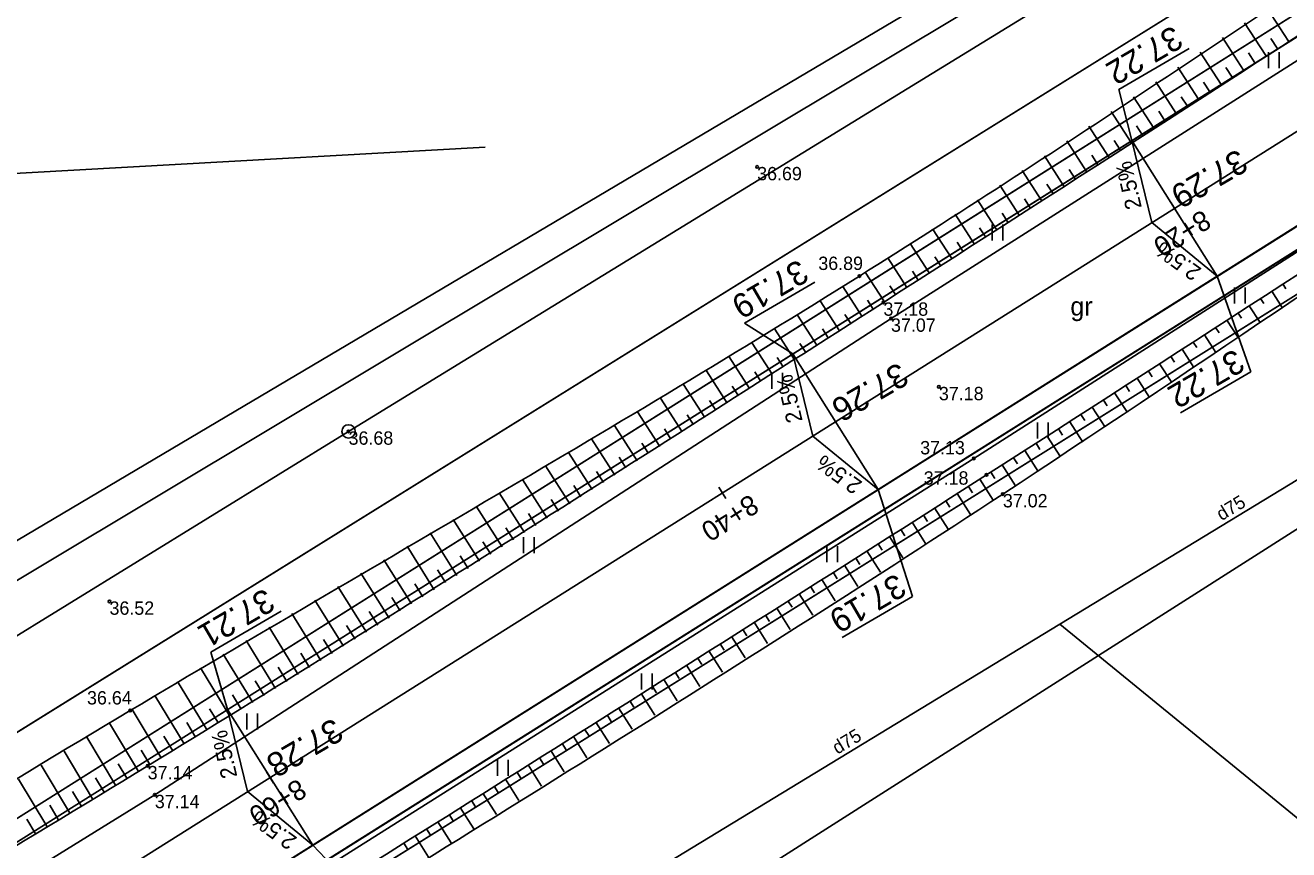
# Model space of a CAD drawing. Extents: x 469981 to 472086, y 246785 to 247785.
# Drawn here: x 471212.38 to 471259.67, y 247263.46 to 247294.34 of the extents above; entities that cross this region are included whole.
import ezdxf

# ---------------------------------------------------------------- set-up
doc = ezdxf.new("R2010")
doc.units = 0
for name, color, linetype in [('0_922', 7, 'Continuous'), ('0_Asfalta_mala', 7, 'Continuous'), ('0_Asfalta_Nomale', 7, 'Continuous'), ('0_Ruut_Braukt', 7, 'Continuous'), ('0_Ruut_nomale', 7, 'Continuous'), ('0_vertikals', 7, 'Continuous'), ('0_vertkals_cipari', 7, 'Continuous'), ('21', 7, 'Continuous'), ('6_piketaza', 7, 'Continuous'), ('CELI_CMAL_####_####_#', 7, 'Continuous'), ('CELI_CSEG_####_TKST_#', 7, 'Continuous'), ('DREN_VADP_####_####_#', 7, 'Continuous'), ('DREN_VADP_KLKT_####_#', 7, 'Continuous'), ('DREN_VADP_KLKT_TKST_#', 7, 'Continuous'), ('ELEK_ELEM_####_####_#', 7, 'Continuous'), ('ELEK_VADV_VSPR_####_#', 7, 'Continuous'), ('RAMI_UZMR_####_####_#', 7, 'Continuous'), ('RELJ_AATZ_####_TKST_#', 7, 'Continuous'), ('RELJ_ELEM_####_####_#', 7, 'Continuous'), ('RELJ_NOGA_####_####_#', 7, 'Continuous'), ('RELJ_NOGL_####_####_#', 7, 'Continuous'), ('ROBZ_IERR_####_####_#', 7, 'Continuous'), ('ROBZ_PROJ_####_####_#', 7, 'Continuous'), ('TERT_ELEM_####_####_#', 7, 'Continuous')]:
    doc.layers.add(name, color=color, linetype=linetype)

msp = doc.modelspace()

# ---------------------------------------------------------------- linework, layer by layer
at = {"layer": '0_922'}
msp.add_line((471337.911, 247339.41), (471145.574, 247218.36), dxfattribs=at)
at = {"layer": '0_Asfalta_mala'}
for p, q in [((471336.304, 247341.944), (471143.977, 247220.899)), ((471339.517, 247336.876), (471147.172, 247215.821))]:
    msp.add_line(p, q, dxfattribs=at)
at = {"layer": '0_Asfalta_Nomale'}
for p, q in [((471335.903, 247342.577), (471143.577, 247221.534)), ((471339.918, 247336.243), (471147.572, 247215.187))]:
    msp.add_line(p, q, dxfattribs=at)
at = {"layer": '0_Ruut_Braukt'}
for p, q in [((471336.304, 247341.944), (471143.977, 247220.899)), ((471147.172, 247215.821), (471339.517, 247336.876))]:
    msp.add_line(p, q, dxfattribs=at)
at = {"layer": '0_Ruut_nomale'}
for points in [[(471512.083, 247454.162), (471511.838, 247454.895), (471453.013, 247417.341), (471348.58, 247350.671), (471335.903, 247342.577), (471306.296, 247323.944), (471248.242, 247287.407), (471208.75, 247262.551), (471208.786, 247261.688), (471290.39, 247313.047), (471335.822, 247341.64), (471349.818, 247350.571), (471398.518, 247381.661), (471437.5, 247406.548), (471498.795, 247445.679), (471511.425, 247453.742)], [(471514.294, 247447.566), (471399.037, 247373.985), (471385.85, 247365.566), (471340.791, 247336.792), (471211.253, 247255.265), (471209.116, 247253.92), (471209.079, 247254.783), (471296.254, 247309.648), (471339.517, 247336.876), (471350.75, 247344.048), (471392.723, 247370.844), (471426.479, 247392.394), (471514.049, 247448.299)]]:
    msp.add_lwpolyline(points, close=True, dxfattribs=at)
at = {"layer": '0_vertikals'}
for p, q in [((471253.314, 247291.937), (471255.945, 247293.472)), ((471253.799, 247290.018), (471253.314, 247291.937)), ((471258.255, 247281.359), (471256.995, 247284.94)), ((471239.303, 247283.18), (471241.935, 247284.715)), ((471241.104, 247282.028), (471239.303, 247283.18)), ((471255.624, 247279.825), (471258.255, 247281.359)), ((471245.589, 247272.951), (471244.3, 247276.95)), ((471242.957, 247271.417), (471245.589, 247272.951)), ((471219.325, 247270.863), (471221.957, 247272.398)), ((471219.945, 247268.712), (471219.325, 247270.863)), ((471225.923, 247260.712), (471223.141, 247263.634))]:
    msp.add_line(p, q, dxfattribs=at)
for points in [[(471253.799, 247290.018), (471254.55, 247286.946), (471256.995, 247284.94)], [(471241.104, 247282.028), (471241.855, 247278.956), (471244.3, 247276.95)], [(471219.945, 247268.712), (471220.697, 247265.64), (471223.141, 247263.634)]]:
    msp.add_lwpolyline(points, close=True, dxfattribs=at)
at = {"layer": '21'}
msp.add_line((471337.911, 247339.41), (471145.574, 247218.36), dxfattribs=at)
at = {"layer": '6_piketaza'}
for points in [[(471255.53, 247287.267), (471255.264, 247287.69)], [(471238.603, 247276.614), (471238.337, 247277.037)], [(471221.677, 247265.961), (471221.41, 247266.384)]]:
    msp.add_lwpolyline(points, dxfattribs=at)
at = {"layer": 'CELI_CMAL_####_####_#'}
for points in [[(471014.161, 247188.048), (471038.308, 247191.645), (471077.61, 247195.71), (471090.836, 247197.337), (471096.461, 247198.582), (471117.856, 247206.682), (471130.197, 247213.261), (471151.631, 247225.738), (471175.407, 247239.608), (471196.168, 247252.49), (471217.229, 247265.52), (471244.784, 247283.359), (471266.102, 247296.914), (471293.433, 247314.365), (471318.262, 247330.084), (471336.637, 247341.969), (471339.45, 247343.841), (471340.412, 247346.293), (471340.291, 247349.818), (471339.894, 247353.24), (471336.901, 247360.015), (471333.813, 247367.721)], [(471347.348, 247327.622), (471345.475, 247334.467), (471344.349, 247336.664), (471343.67, 247337.19), (471342.054, 247337.492), (471341.155, 247337.494), (471339.762, 247336.569), (471318.941, 247323.623), (471297.221, 247309.64), (471268.834, 247291.51), (471247.888, 247278.119), (471219.179, 247259.989), (471200.048, 247247.93), (471177.515, 247234.149), (471154.773, 247220.961), (471131.272, 247207.521), (471119.66, 247201.466), (471103.03, 247195.231), (471092.329, 247192.658), (471077.436, 247189.782), (471058.729, 247187.944), (471037.006, 247184.759), (471015.923, 247182.598), (470992.26, 247181.035)]]:
    msp.add_lwpolyline(points, dxfattribs=at)
at = {"layer": 'DREN_VADP_####_####_#'}
for points in [[(471137.599, 247228.901), (471310.269, 247332.452)], [(471229.592, 247289.778), (471189.418, 247287.521)], [(471271.382, 247255.353), (471251.107, 247271.912)]]:
    msp.add_lwpolyline(points, dxfattribs=at)
at = {"layer": 'DREN_VADP_KLKT_####_#'}
msp.add_lwpolyline([(471222.566, 247254.545), (471236.742, 247263.171), (471251.107, 247271.912), (471265.735, 247280.811), (471282.069, 247290.749), (471296.434, 247299.489), (471310.919, 247308.304), (471326.918, 247318.037)], dxfattribs=at)
at = {"layer": 'ELEK_ELEM_####_####_#'}
msp.add_circle((471224.48, 247279.13), 0.25, dxfattribs=at)
at = {"layer": 'ELEK_VADV_VSPR_####_#'}
for p, q in [((471224.48, 247279.13), (471279.662, 247313.004)), ((471169.047, 247244.988), (471224.48, 247279.13))]:
    msp.add_line(p, q, dxfattribs=at)
at = {"layer": 'RAMI_UZMR_####_####_#'}
for points in [[(471010.572, 247199.465), (471044.448, 247201.846), (471094.566, 247205.368), (471219.251, 247279.294), (471287.982, 247320.045), (471329.582, 247346.385), (471332.466, 247352.407), (471329.951, 247358.592), (471331.784, 247361.204), (471339.558, 247364.746), (471343.514, 247360.959), (471346.629, 247357.978), (471355.9, 247363.1), (471457.4, 247429.3)], [(471380.292, 247353.371), (471352.036, 247335.759), (471352.913, 247327.325), (471347.47, 247325.392), (471345.187, 247325.919), (471342.905, 247329.082), (471319.551, 247313.443), (471222.661, 247251.69), (471157.352, 247211.35), (471144.207, 247202.916), (471131.364, 247196.59), (471113.303, 247188.858), (471105.677, 247188.256), (471083.576, 247183.01), (471075.205, 247182.665), (471043.397, 247175.418), (471016.707, 247172.079), (470997.217, 247171.376)]]:
    msp.add_lwpolyline(points, dxfattribs=at)
at = {"layer": 'RELJ_ELEM_####_####_#'}
for centre in [(471239.774, 247289.031), (471243.601, 247284.946), (471244.501, 247283.959), (471244.784, 247283.359), (471246.577, 247280.796), (471224.48, 247279.13), (471247.888, 247278.119), (471248.359, 247277.5), (471248.971, 247276.784), (471215.532, 247272.762), (471216.311, 247268.677), (471216.962, 247266.603), (471217.229, 247265.52)]:
    msp.add_circle(centre, 0.05, dxfattribs=at)
at = {"layer": 'RELJ_NOGA_####_####_#'}
for p, q in [((471259.656, 247293.747), (471258.852, 247294.988)), ((471258.816, 247293.203), (471258.02, 247294.434)), ((471257.977, 247292.66), (471257.188, 247293.88)), ((471259.236, 247293.475), (471258.996, 247293.846)), ((471257.137, 247292.117), (471256.355, 247293.325)), ((471258.396, 247292.932), (471258.159, 247293.299)), ((471256.297, 247291.574), (471255.523, 247292.771)), ((471257.557, 247292.389), (471257.321, 247292.753)), ((471255.457, 247291.031), (471254.691, 247292.217)), ((471256.717, 247291.845), (471256.484, 247292.206)), ((471254.618, 247290.488), (471253.858, 247291.663)), ((471255.877, 247291.302), (471255.646, 247291.66)), ((471253.778, 247289.945), (471253.025, 247291.109)), ((471255.038, 247290.76), (471254.809, 247291.114)), ((471252.938, 247289.402), (471252.193, 247290.556)), ((471254.198, 247290.217), (471253.971, 247290.567)), ((471252.098, 247288.86), (471251.359, 247290.004)), ((471253.358, 247289.674), (471253.133, 247290.021)), ((471251.258, 247288.317), (471250.525, 247289.453)), ((471252.518, 247289.131), (471252.295, 247289.476)), ((471250.418, 247287.775), (471249.69, 247288.902)), ((471251.678, 247288.588), (471251.457, 247288.93)), ((471249.578, 247287.232), (471248.854, 247288.353)), ((471250.838, 247288.046), (471250.619, 247288.385)), ((471248.737, 247286.69), (471248.018, 247287.805)), ((471249.998, 247287.504), (471249.78, 247287.841)), ((471247.897, 247286.148), (471247.181, 247287.258)), ((471249.158, 247286.961), (471248.941, 247287.297)), ((471248.317, 247286.419), (471248.102, 247286.753)), ((471247.057, 247285.606), (471246.343, 247286.713)), ((471246.216, 247285.064), (471245.504, 247286.169)), ((471247.477, 247285.877), (471247.263, 247286.21)), ((471245.376, 247284.523), (471244.664, 247285.627)), ((471246.636, 247285.335), (471246.423, 247285.667)), ((471244.535, 247283.981), (471243.822, 247285.087)), ((471245.796, 247284.794), (471245.582, 247285.125)), ((471243.695, 247283.439), (471242.979, 247284.55)), ((471244.955, 247284.252), (471244.742, 247284.583)), ((471259.452, 247284.649), (471259.568, 247284.471)), ((471242.854, 247282.898), (471242.133, 247284.016)), ((471244.115, 247283.71), (471243.901, 247284.043)), ((471258.613, 247284.105), (471258.733, 247283.921)), ((471259.033, 247284.377), (471259.424, 247283.773)), ((471242.013, 247282.356), (471241.285, 247283.486)), ((471243.274, 247283.169), (471243.059, 247283.503)), ((471257.774, 247283.561), (471257.897, 247283.37)), ((471258.194, 247283.833), (471258.599, 247283.208)), ((471256.935, 247283.017), (471257.062, 247282.82)), ((471257.354, 247283.289), (471257.772, 247282.644)), ((471241.173, 247281.814), (471240.435, 247282.96)), ((471242.434, 247282.627), (471242.216, 247282.964)), ((471256.515, 247282.745), (471256.946, 247282.08)), ((471240.332, 247281.273), (471239.582, 247282.436)), ((471241.593, 247282.085), (471241.373, 247282.426)), ((471255.676, 247282.202), (471256.119, 247281.517)), ((471256.095, 247282.473), (471256.226, 247282.271)), ((471239.491, 247280.731), (471238.728, 247281.916)), ((471240.752, 247281.544), (471240.529, 247281.89)), ((471254.836, 247281.659), (471255.29, 247280.956)), ((471255.256, 247281.93), (471255.39, 247281.722)), ((471238.65, 247280.19), (471237.873, 247281.399)), ((471239.912, 247281.002), (471239.685, 247281.354)), ((471253.996, 247281.117), (471254.461, 247280.396)), ((471254.416, 247281.388), (471254.554, 247281.174)), ((471237.81, 247279.649), (471237.015, 247280.884)), ((471239.071, 247280.461), (471238.84, 247280.82)), ((471253.576, 247280.845), (471253.716, 247280.627)), ((471236.968, 247279.108), (471236.157, 247280.371)), ((471238.23, 247279.92), (471237.994, 247280.286)), ((471252.735, 247280.304), (471252.879, 247280.081)), ((471253.155, 247280.575), (471253.63, 247279.838)), ((471236.127, 247278.568), (471235.297, 247279.861)), ((471237.389, 247279.379), (471237.148, 247279.753)), ((471251.894, 247279.763), (471252.04, 247279.536)), ((471252.314, 247280.033), (471252.797, 247279.282)), ((471235.285, 247278.029), (471234.437, 247279.352)), ((471236.547, 247278.838), (471236.302, 247279.222)), ((471251.053, 247279.222), (471251.2, 247278.992)), ((471251.473, 247279.492), (471251.964, 247278.73)), ((471234.443, 247277.489), (471233.575, 247278.846)), ((471250.632, 247278.952), (471251.127, 247278.179)), ((471233.6, 247276.951), (471232.713, 247278.34)), ((471235.706, 247278.298), (471235.454, 247278.691)), ((471249.789, 247278.413), (471250.289, 247277.633)), ((471250.211, 247278.683), (471250.36, 247278.45)), ((471232.757, 247276.413), (471231.85, 247277.836)), ((471234.864, 247277.759), (471234.606, 247278.161)), ((471248.947, 247277.875), (471249.448, 247277.089)), ((471249.368, 247278.144), (471249.518, 247277.909)), ((471231.914, 247275.875), (471230.986, 247277.333)), ((471234.022, 247277.22), (471233.758, 247277.632)), ((471248.103, 247277.337), (471248.605, 247276.55)), ((471248.525, 247277.606), (471248.676, 247277.37)), ((471231.07, 247275.339), (471230.122, 247276.831)), ((471233.179, 247276.681), (471232.909, 247277.103)), ((471247.682, 247277.069), (471247.832, 247276.833)), ((471232.336, 247276.144), (471232.06, 247276.576)), ((471246.838, 247276.532), (471246.989, 247276.295)), ((471247.26, 247276.8), (471247.762, 247276.012)), ((471230.226, 247274.803), (471229.258, 247276.329)), ((471231.492, 247275.607), (471231.211, 247276.049)), ((471245.994, 247275.996), (471246.145, 247275.758)), ((471246.416, 247276.264), (471246.918, 247275.474)), ((471229.381, 247274.268), (471228.395, 247275.828)), ((471230.648, 247275.071), (471230.361, 247275.524)), ((471245.15, 247275.459), (471245.301, 247275.222)), ((471245.572, 247275.727), (471246.075, 247274.936)), ((471228.535, 247273.734), (471227.531, 247275.327)), ((471229.803, 247274.535), (471229.51, 247274.998)), ((471244.728, 247275.191), (471245.231, 247274.399)), ((471227.689, 247273.201), (471226.668, 247274.826)), ((471228.958, 247274.001), (471228.659, 247274.474)), ((471243.884, 247274.655), (471244.387, 247273.861)), ((471244.306, 247274.923), (471244.457, 247274.685)), ((471226.842, 247272.67), (471225.805, 247274.323)), ((471243.039, 247274.12), (471243.543, 247273.325)), ((471243.461, 247274.388), (471243.613, 247274.149)), ((471225.994, 247272.139), (471224.943, 247273.822)), ((471228.112, 247273.468), (471227.808, 247273.95)), ((471242.194, 247273.585), (471242.699, 247272.788)), ((471242.617, 247273.852), (471242.768, 247273.613)), ((471225.146, 247271.609), (471224.081, 247273.319)), ((471227.266, 247272.935), (471226.957, 247273.427)), ((471241.35, 247273.049), (471241.855, 247272.252)), ((471241.772, 247273.317), (471241.923, 247273.078)), ((471224.297, 247271.081), (471223.22, 247272.815)), ((471226.418, 247272.404), (471226.105, 247272.905)), ((471240.927, 247272.782), (471241.079, 247272.543)), ((471223.447, 247270.554), (471222.362, 247272.31)), ((471225.57, 247271.874), (471225.253, 247272.383)), ((471240.082, 247272.247), (471240.234, 247272.008)), ((471240.505, 247272.515), (471241.01, 247271.716)), ((471222.596, 247270.029), (471221.503, 247271.804)), ((471224.722, 247271.345), (471224.401, 247271.862)), ((471239.237, 247271.713), (471239.389, 247271.473)), ((471239.66, 247271.98), (471240.165, 247271.181)), ((471221.745, 247269.505), (471220.645, 247271.295)), ((471223.872, 247270.818), (471223.548, 247271.341)), ((471238.392, 247271.178), (471238.543, 247270.938)), ((471238.814, 247271.446), (471239.32, 247270.646)), ((471220.892, 247268.982), (471219.789, 247270.785)), ((471223.022, 247270.291), (471222.695, 247270.821)), ((471237.969, 247270.911), (471238.475, 247270.111)), ((471220.038, 247268.461), (471218.934, 247270.272)), ((471222.171, 247269.767), (471221.841, 247270.301)), ((471237.124, 247270.377), (471237.63, 247269.576)), ((471237.546, 247270.644), (471237.698, 247270.404)), ((471219.184, 247267.942), (471218.082, 247269.758)), ((471221.318, 247269.243), (471220.988, 247269.783)), ((471236.278, 247269.844), (471236.784, 247269.042)), ((471236.701, 247270.111), (471236.852, 247269.87)), ((471220.465, 247268.722), (471220.135, 247269.264)), ((471235.432, 247269.31), (471235.938, 247268.508)), ((471235.855, 247269.577), (471236.007, 247269.336)), ((471218.328, 247267.424), (471217.231, 247269.241)), ((471235.009, 247269.043), (471235.161, 247268.803)), ((471217.471, 247266.909), (471216.382, 247268.721)), ((471219.611, 247268.201), (471219.28, 247268.746)), ((471234.163, 247268.51), (471234.315, 247268.269)), ((471234.586, 247268.777), (471235.092, 247267.974)), ((471216.614, 247266.395), (471215.534, 247268.199)), ((471218.756, 247267.683), (471218.426, 247268.228)), ((471233.317, 247267.977), (471233.469, 247267.736)), ((471233.74, 247268.243), (471234.246, 247267.441)), ((471215.756, 247265.881), (471214.682, 247267.675)), ((471217.9, 247267.166), (471217.572, 247267.711)), ((471232.471, 247267.444), (471232.623, 247267.203)), ((471232.894, 247267.71), (471233.399, 247266.908)), ((471214.898, 247265.367), (471213.831, 247267.151)), ((471217.043, 247266.651), (471216.717, 247267.194)), ((471231.625, 247266.911), (471231.776, 247266.671)), ((471232.048, 247267.177), (471232.553, 247266.376)), ((471214.039, 247264.854), (471212.98, 247266.627)), ((471216.185, 247266.138), (471215.862, 247266.677)), ((471231.202, 247266.645), (471231.706, 247265.844)), ((471213.181, 247264.341), (471212.128, 247266.103)), ((471215.327, 247265.624), (471215.006, 247266.161)), ((471230.356, 247266.112), (471230.859, 247265.312)), ((471230.779, 247266.378), (471230.93, 247266.138)), ((471214.468, 247265.111), (471214.15, 247265.644)), ((471229.509, 247265.579), (471230.012, 247264.781)), ((471229.932, 247265.846), (471230.083, 247265.606)), ((471213.61, 247264.598), (471213.293, 247265.128)), ((471228.663, 247265.047), (471229.164, 247264.249)), ((471229.086, 247265.313), (471229.237, 247265.074)), ((471212.752, 247264.085), (471212.437, 247264.612)), ((471228.24, 247264.781), (471228.39, 247264.542)), ((471227.393, 247264.248), (471227.543, 247264.01)), ((471227.816, 247264.514), (471228.317, 247263.719)), ((471226.546, 247263.716), (471226.696, 247263.478)), ((471226.97, 247263.982), (471227.469, 247263.189))]:
    msp.add_line(p, q, dxfattribs=at)
for points in [[(471170.189, 247238.813), (471187.045, 247248.806), (471216.962, 247266.603), (471244.501, 247283.959), (471265.809, 247297.732), (471292.77, 247315.312), (471318.062, 247330.842), (471332.326, 247339.791), (471337.257, 247343.054), (471338.429, 247344.75), (471338.591, 247346.479)], [(471155.25, 247220.273), (471177.77, 247233.339), (471200.51, 247247.391), (471219.6, 247259.351), (471248.359, 247277.5), (471269.232, 247290.973), (471319.351, 247322.992), (471333.341, 247331.731), (471337.475, 247334.177), (471338.538, 247334.697), (471340.216, 247335.099), (471340.901, 247334.839)]]:
    msp.add_spline(points, degree=3, dxfattribs=at)
at = {"layer": 'RELJ_NOGL_####_####_#'}
for points in [[(471337.22, 247346.431), (471336.644, 247345.408), (471332.13, 247341.491), (471317.859, 247332.101), (471292.129, 247316.676), (471265.206, 247299.186), (471243.601, 247284.946), (471216.311, 247268.677), (471186.292, 247250.183), (471169.475, 247239.793)], [(471155.819, 247219.592), (471177.985, 247232.653), (471201.025, 247246.801), (471219.926, 247258.493), (471248.971, 247276.784), (471269.467, 247290.521), (471319.665, 247322.242), (471333.631, 247330.726), (471337.921, 247333.442), (471339.285, 247334.228), (471340.237, 247334.435), (471340.94, 247334.352)]]:
    msp.add_spline(points, degree=3, dxfattribs=at)
at = {"layer": 'ROBZ_IERR_####_####_#'}
for points in [[(471513.259, 247488.166), (471524.883, 247464.852), (471341.261, 247348.2), (471124.72, 247213.54), (471093.674, 247200.298), (471050.609, 247195.379), (471001.509, 247189.266), (470977.922, 247249.601)], [(471168.816, 247177.651), (471133.176, 247205.05), (471346.741, 247338.478), (471363.107, 247281.069)]]:
    msp.add_lwpolyline(points, dxfattribs=at)
at = {"layer": 'ROBZ_PROJ_####_####_#'}
for points in [[(470613.752, 247179.765), (470688.303, 247197.106), (470783.692, 247219.293), (470809.088, 247224.67), (470845.751, 247226.447), (470876.169, 247225.296), (470921.641, 247209.731), (470967.353, 247194.084), (470989.48, 247188.802), (471001.509, 247189.266), (471050.609, 247195.379), (471093.674, 247200.298), (471124.72, 247213.54), (471341.261, 247348.2), (471524.883, 247464.852)], [(471398.351, 247372.094), (471346.741, 247338.478), (471133.176, 247205.05), (471108.425, 247194.786), (471087.339, 247189.709), (471023.306, 247181.157), (470962.604, 247185.245), (470905.63, 247205.857), (470878.75, 247214.454), (470852.344, 247217.039), (470815.743, 247215.147), (470778.583, 247209.26), (470718.669, 247194.633), (470636.973, 247175.147), (470468.364, 247124.23), (470431.624, 247112.202), (470396.219, 247097.502), (470371.503, 247083.47), (470275.956, 246992.729), (470152.342, 246907.761), (470066.737, 246851.23)]]:
    msp.add_lwpolyline(points, dxfattribs=at)
at = {"layer": 'TERT_ELEM_####_####_#'}
for p, q in [((471258.916, 247292.731), (471258.916, 247293.331)), ((471259.316, 247292.731), (471259.316, 247293.331)), ((471248.569, 247286.278), (471248.569, 247286.878)), ((471248.969, 247286.278), (471248.969, 247286.878)), ((471257.635, 247283.921), (471257.635, 247284.521)), ((471258.035, 247283.921), (471258.035, 247284.521)), ((471240.321, 247280.725), (471240.321, 247281.325)), ((471240.721, 247280.725), (471240.721, 247281.325)), ((471250.265, 247278.862), (471250.265, 247279.462)), ((471250.665, 247278.862), (471250.665, 247279.462)), ((471231.024, 247274.573), (471231.024, 247275.173)), ((471231.424, 247274.573), (471231.424, 247275.173)), ((471242.382, 247274.231), (471242.382, 247274.831)), ((471242.782, 247274.231), (471242.782, 247274.831)), ((471235.441, 247269.468), (471235.441, 247270.068)), ((471235.841, 247269.468), (471235.841, 247270.068)), ((471220.676, 247267.97), (471220.676, 247268.57)), ((471221.076, 247267.97), (471221.076, 247268.57)), ((471230.054, 247266.234), (471230.054, 247266.834)), ((471230.454, 247266.234), (471230.454, 247266.834))]:
    msp.add_line(p, q, dxfattribs=at)

# ---------------------------------------------------------------- texts
at = {"layer": '0_vertkals_cipari'}
for s, height, rotation, p in [('37.22', 0.9, 210.2507, (471255.348, 247294.357)), ('37.29', 0.9, 210.2507, (471257.774, 247289.731)), ('2.5%', 0.5993, 103.0344, (471254.174, 247287.514)), ('2.5%', 0.5993, 144.2467, (471256.44, 247285.211)), ('37.19', 0.9, 210.2507, (471241.337, 247285.6)), ('37.22', 0.9, 210.2507, (471257.658, 247282.245)), ('37.26', 0.9, 210.2507, (471245.079, 247281.741)), ('2.5%', 0.5993, 103.0344, (471241.479, 247279.524)), ('2.5%', 0.5993, 144.2467, (471243.745, 247277.221)), ('37.19', 0.9, 210.2507, (471244.991, 247273.837)), ('37.21', 0.9, 210.2507, (471221.359, 247273.283)), ('37.28', 0.9, 210.2507, (471223.92, 247268.425)), ('2.5%', 0.5993, 103.0344, (471220.321, 247266.208)), ('2.5%', 0.5993, 144.2467, (471222.587, 247263.905))]:
    msp.add_text(s, height=height, rotation=rotation, dxfattribs=at).set_placement(p)
at = {"layer": '6_piketaza'}
for s, p in [('8+20', (471256.443, 247287.457)), ('8+40', (471239.516, 247276.804)), ('8+60', (471222.589, 247266.151))]:
    msp.add_text(s, height=0.75, rotation=212.1849, dxfattribs=at).set_placement(p)
at = {"layer": 'CELI_CSEG_####_TKST_#'}
msp.add_text('gr', height=0.7, dxfattribs=at).set_placement((471251.498, 247283.464))
at = {"layer": 'DREN_VADP_KLKT_TKST_#'}
for rotation, p in [(31.317, (471257.155, 247275.767)), (31.3178, (471242.779, 247267.02))]:
    msp.add_text('d75', height=0.5, rotation=rotation, dxfattribs=at).set_placement(p)
at = {"layer": 'RELJ_AATZ_####_TKST_#'}
for s, p in [('36.69', (471239.774, 247288.531)), ('36.89', (471242.062, 247285.173)), ('37.18', (471244.501, 247283.459)), ('37.07', (471244.784, 247282.859)), ('37.18', (471246.577, 247280.296)), ('36.68', (471224.48, 247278.63)), ('37.13', (471245.876, 247278.269)), ('37.18', (471246.009, 247277.134)), ('37.02', (471248.971, 247276.284)), ('36.52', (471215.532, 247272.262)), ('36.64', (471214.691, 247268.903)), ('37.14', (471216.962, 247266.103)), ('37.14', (471217.229, 247265.02))]:
    msp.add_text(s, height=0.5, dxfattribs=at).set_placement(p)

doc.saveas('drawing.dxf')
